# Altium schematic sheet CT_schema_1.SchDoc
size 443 x 258 mm
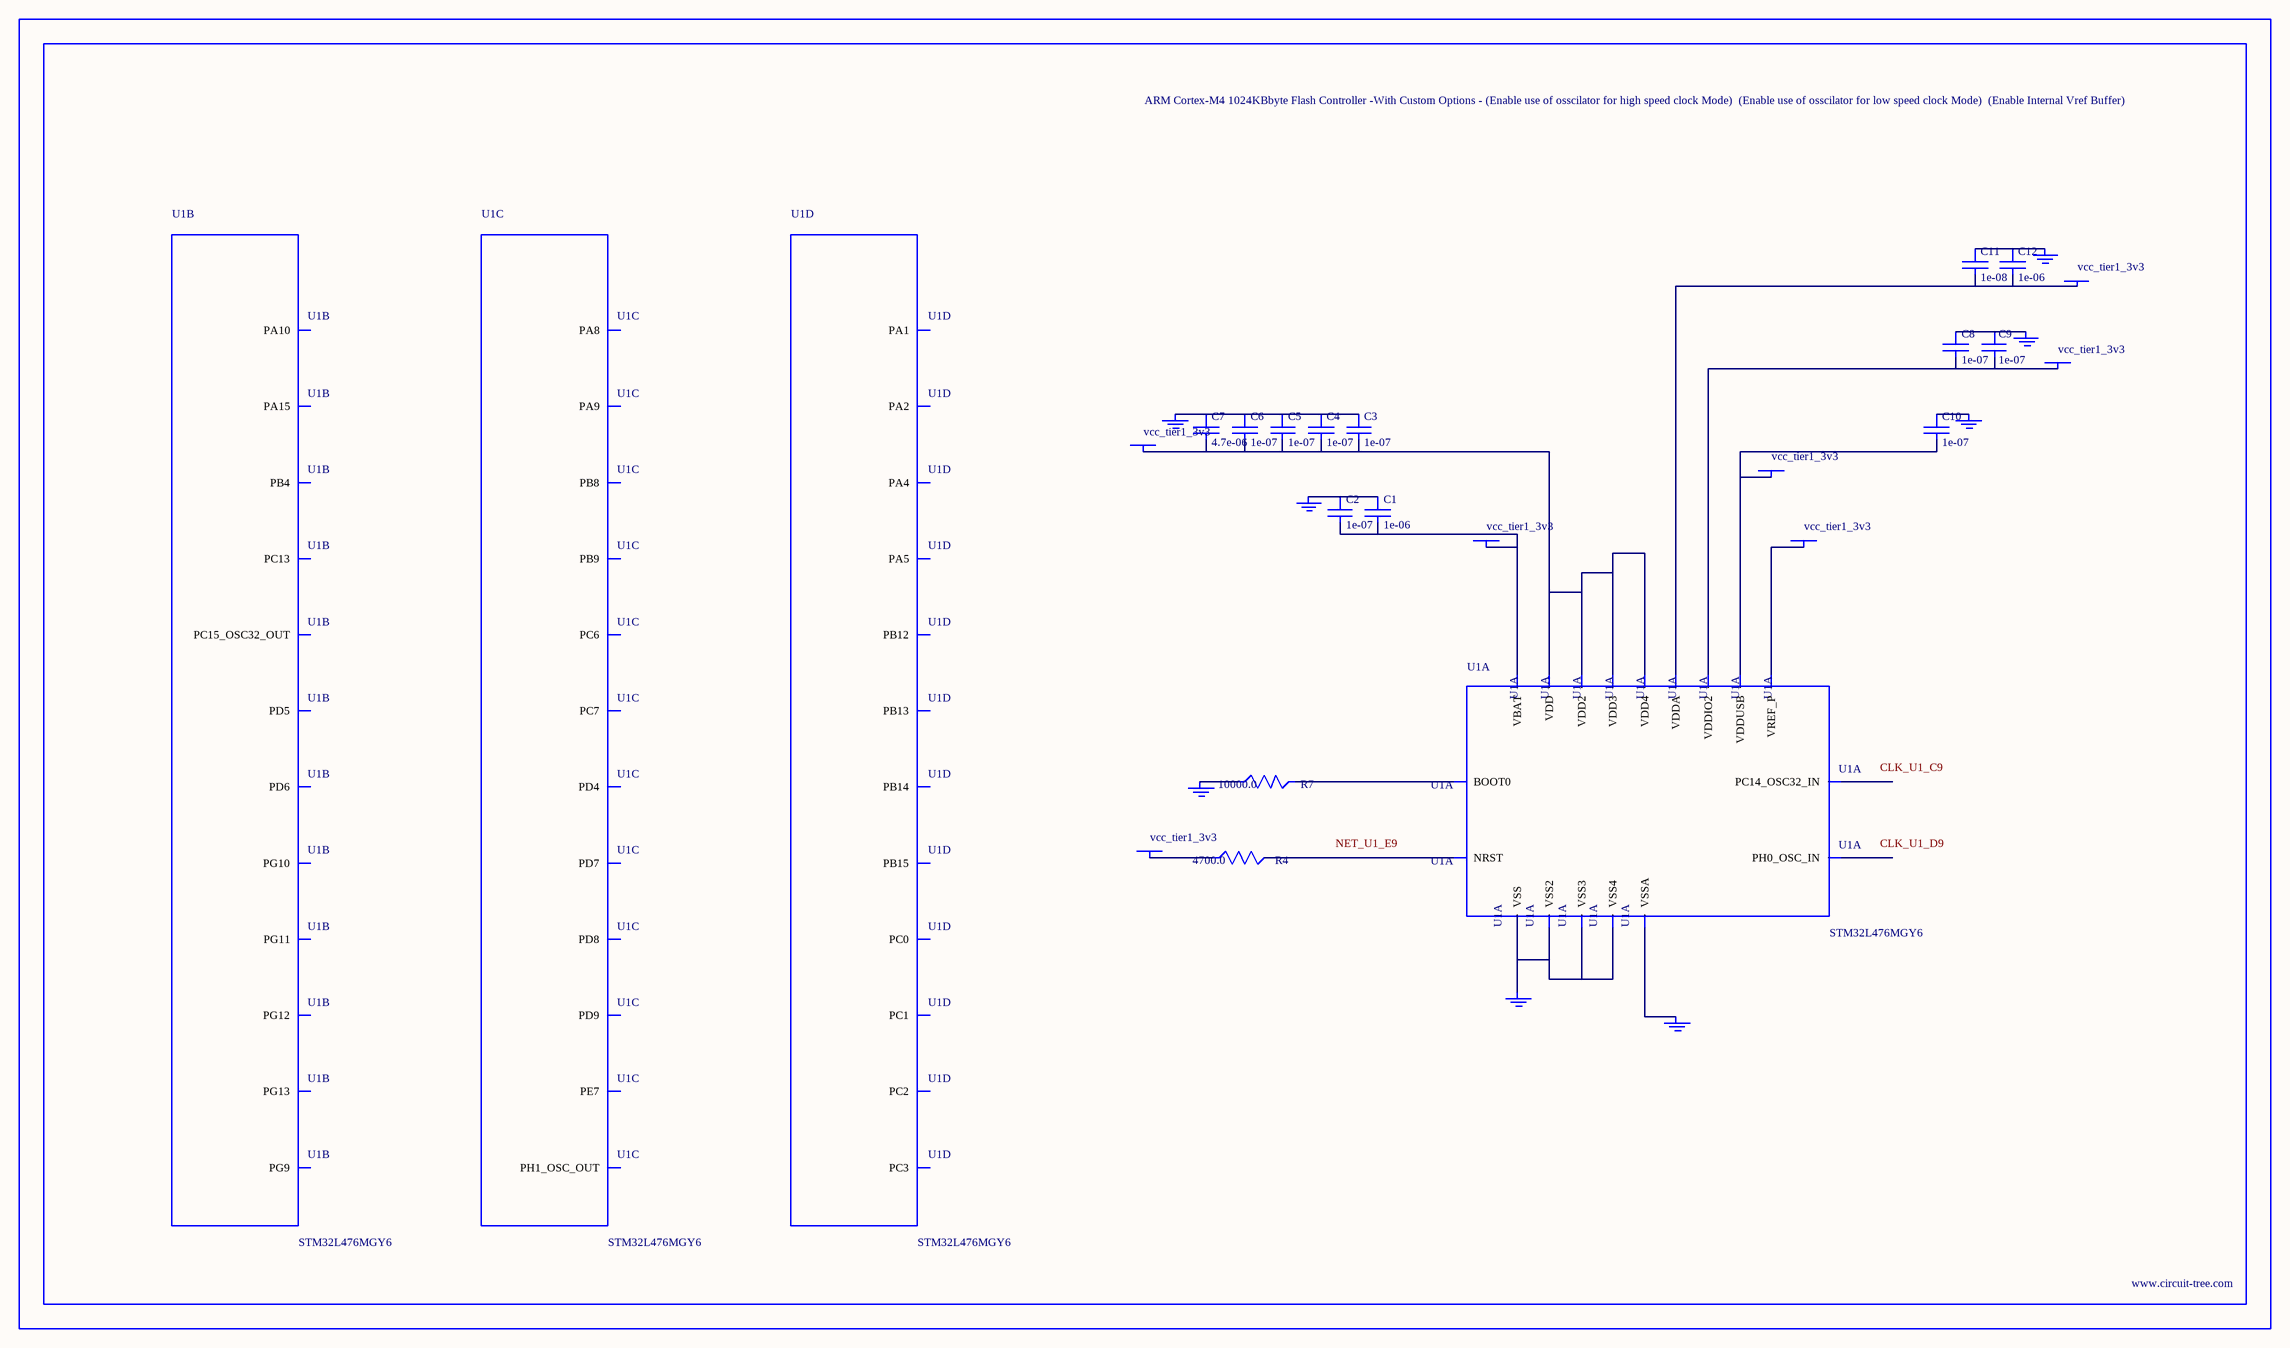
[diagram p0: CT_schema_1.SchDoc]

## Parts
BORDER0  (no value)
C1  1e-06  [C0603]
C2  1e-07  [C0603]
C3  1e-07  [C0603]
C4  1e-07  [C0603]
C5  1e-07  [C0603]
C6  1e-07  [C0603]
C7  4.7e-06  [C0603]
C8  1e-07  [C0603]
C9  1e-07  [C0603]
C10  1e-07  [C0603]
C11  1e-08  [C0603]
C12  1e-06  [C0603]
GND_INSTANCE_0_0  (no value)
GND_INSTANCE_0_1  (no value)
GND_INSTANCE_0_2  (no value)
GND_INSTANCE_0_3  (no value)
GND_INSTANCE_0_4  (no value)
GND_INSTANCE_0_5  (no value)
GND_INSTANCE_0_6  (no value)
GND_INSTANCE_0_7  (no value)
POWER_INSTANCE_0_0  vcc_tier1_3v3
POWER_INSTANCE_0_1  vcc_tier1_3v3
POWER_INSTANCE_0_2  vcc_tier1_3v3
POWER_INSTANCE_0_3  vcc_tier1_3v3
POWER_INSTANCE_0_4  vcc_tier1_3v3
POWER_INSTANCE_0_5  vcc_tier1_3v3
POWER_INSTANCE_0_6  vcc_tier1_3v3
R4  4700.0  [R0603]
R7  10000.0  [R0603]
U1  STM32L476MGY6  [WLCSP81]  (parts A,B,C,D of 10)

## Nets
NetC1_1: C1.1 C2.1 GND_INSTANCE_0_0.0(GND)
NetC1_2: C1.2 C2.2 POWER_INSTANCE_0_0.0(PWR) U1.B9(VBAT)
NetC3_1: C3.1 C4.1 C5.1 C6.1 C7.1 GND_INSTANCE_0_1.0(GND)
NetC3_2: C3.2 C4.2 C5.2 C6.2 C7.2 POWER_INSTANCE_0_1.0(PWR) U1.A9(VDD) U1.E4(VDD2) U1.J1(VDD3) U1.J8(VDD4)
NetC8_1: C8.1 C9.1 GND_INSTANCE_0_2.0(GND)
NetC8_2: C8.2 C9.2 POWER_INSTANCE_0_2.0(PWR) U1.B6(VDDIO2)
NetC10_1: C10.1 GND_INSTANCE_0_4.0(GND)
NetC10_2: C10.2 POWER_INSTANCE_0_3.0(PWR) U1.A1(VDDUSB)
NetC11_1: C11.1 C12.1 GND_INSTANCE_0_5.0(GND)
NetC11_2: C11.2 C12.2 POWER_INSTANCE_0_4.0(PWR) U1.H9(VDDA)
NetGND_INSTANCE_0_3_0: GND_INSTANCE_0_3.0(GND) R7.1
NetGND_INSTANCE_0_6_0: GND_INSTANCE_0_6.0(GND) U1.G9(VSSA)
NetGND_INSTANCE_0_7_0: GND_INSTANCE_0_7.0(GND) U1.A8(VSS) U1.B1(VSS2) U1.J2(VSS3) U1.J9(VSS4)
NetPOWER_INSTANCE_0_5_0: POWER_INSTANCE_0_5.0(PWR) U1.G8(VREF_P)
NetPOWER_INSTANCE_0_6_0: POWER_INSTANCE_0_6.0(PWR) R4.1
NetR4_2: R4.2 U1.E9(NRST)
NetR7_2: R7.2 U1.D7(BOOT0)

Not connected (* = marked no-connect by the designer): U1 A2(PA15) A4(PG9) B4(PG10) B5(PG13) B8(PC13) C4(PG11) C5(PG12) C6(PB4) C8(PC15_OSC32_OUT) C9(PC14_OSC32_IN) D2(PA10) D4(PD5) D5(PD6) D6(PD7) D8(PH1_OSC_OUT) D9(PH0_OSC_IN) E2(PA8) E3(PA9) E5(PD4) E6(PE7) E7(PB8) E8(PB9) F1(PC7) F3(PC6) F4(PD9) F5(PD8) F7(PC2) F8(PC1) F9(PC0) G1(PB15) G2(PB14) G4(PA1) G5(PA4) G6(PA2) G7(PC3) H1(PB12) H2(PB13) H6(PA5)

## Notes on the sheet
- Labels drawn without touching a wire or pin: CLK_U1_C9, CLK_U1_D9, NET_U1_E9

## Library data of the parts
BORDER0 = BORDER_PAGE0
C1 C12 = C0603C105K3RACTU
C2-C6 C8-C10 = 06035C104K4Z2A
C7 = GRM188R6YA475KE15D
C11 = 06035C103K4Z2A
GND_INSTANCE_0_0-GND_INSTANCE_0_7 = GND
POWER_INSTANCE_0_0-POWER_INSTANCE_0_6 = PWR
R4 = RC0603JR-074K7L
R7 = RC0603JR-0710KL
